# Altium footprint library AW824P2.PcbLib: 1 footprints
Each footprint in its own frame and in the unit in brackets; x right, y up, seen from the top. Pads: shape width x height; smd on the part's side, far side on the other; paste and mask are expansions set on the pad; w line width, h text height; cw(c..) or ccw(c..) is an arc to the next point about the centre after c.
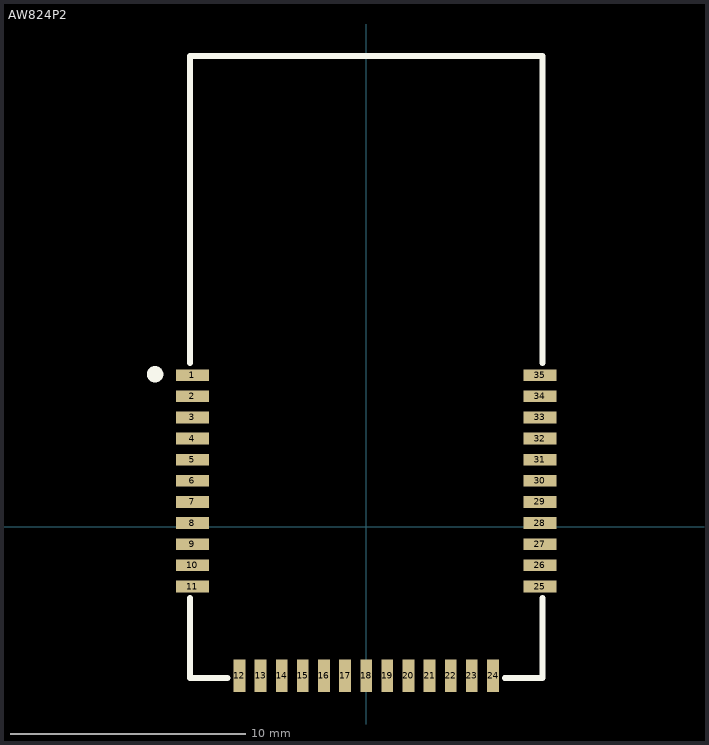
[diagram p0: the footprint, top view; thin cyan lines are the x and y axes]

## AW824P2 [mm]
pads (35):
  rect 1.4x0.5 smd mask+0.038: 1(-7.4,6.45) 2(-7.4,5.55) 3(-7.4,4.65) 4(-7.4,3.75) 5(-7.4,2.85) 6(-7.4,1.95) 7(-7.4,1.05) 8(-7.4,0.15) 9(-7.4,-0.75) 10(-7.4,-1.65) 11(-7.4,-2.55) 25(7.4,-2.55) 26(7.4,-1.65) 27(7.4,-0.75) 28(7.4,0.15) 29(7.4,1.05) 30(7.4,1.95) 31(7.4,2.85) 32(7.4,3.75) 33(7.4,4.65) 34(7.4,5.55) 35(7.4,6.45)
  rect 0.5x1.4 smd mask+0.038: 12(-5.4,-6.35) 13(-4.5,-6.35) 14(-3.6,-6.35) 15(-2.7,-6.35) 16(-1.8,-6.35) 17(-0.9,-6.35) 18(0,-6.35) 19(0.9,-6.35) 20(1.8,-6.35) 21(2.7,-6.35) 22(3.6,-6.35) 23(4.5,-6.35) 24(5.4,-6.35)
Top Overlay:
  circle w0.4: c-8.989,6.488 r0.15
  lines w0.254: -7.5,-3.046 -7.5,-6.45 -5.9,-6.45 ; -7.5,6.961 -7.5,20.05 7.5,20.05 7.5,6.961 ; 5.9,-6.45 7.5,-6.45 7.5,-3.046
